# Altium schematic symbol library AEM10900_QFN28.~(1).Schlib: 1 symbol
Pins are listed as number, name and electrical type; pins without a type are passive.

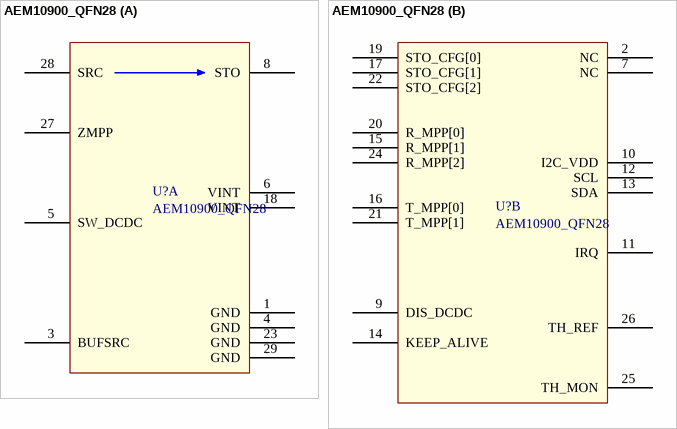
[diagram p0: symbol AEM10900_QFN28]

## AEM10900_QFN28
designator U?
part A pins: 1 GND, 3 BUFSRC, 4 GND, 5 SW_DCDC, 6 VINT, 8 STO, 18 VINT, 23 GND, 27 ZMPP, 28 SRC (power), 29 GND
part B pins: 2 NC, 7 NC, 9 DIS_DCDC, 10 I2C_VDD, 11 IRQ, 12 SCL, 13 SDA, 14 KEEP_ALIVE, 15 R_MPP[1], 16 T_MPP[0], 17 STO_CFG[1], 19 STO_CFG[0], 20 R_MPP[0], 21 T_MPP[1], 22 STO_CFG[2], 24 R_MPP[2], 25 TH_MON, 26 TH_REF (power)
